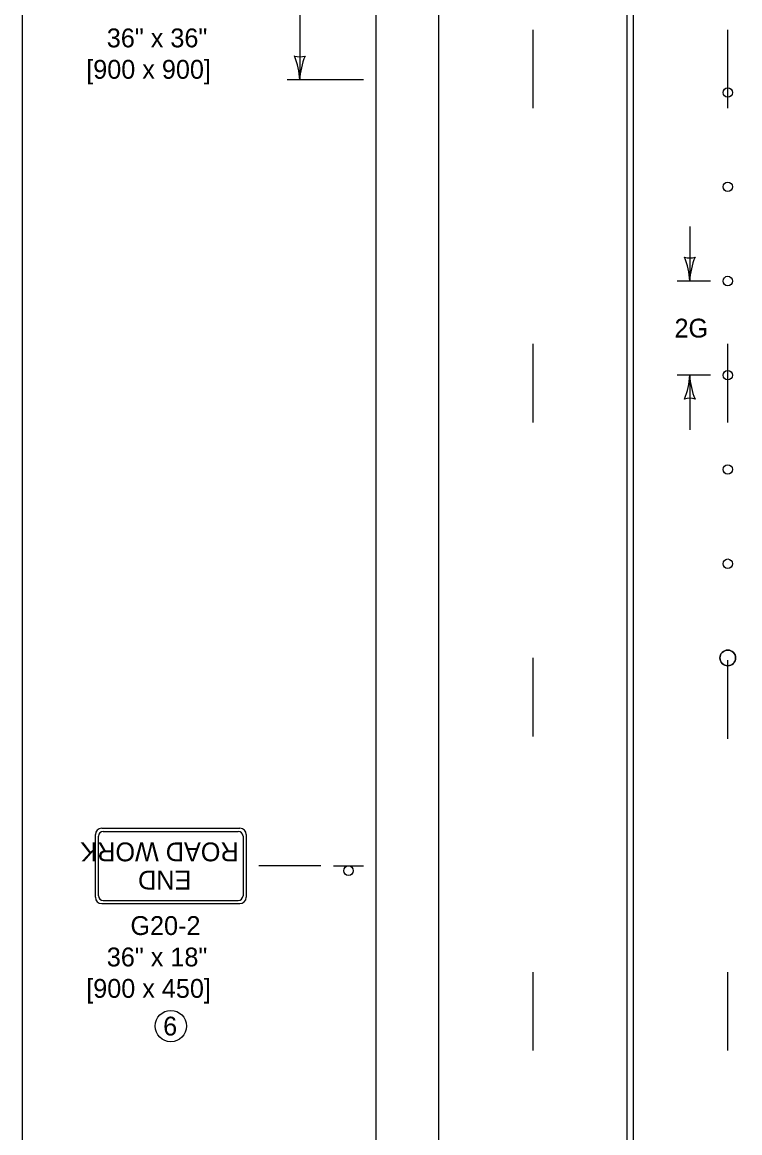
# Model space of a CAD drawing. Extents: x 49991.4 to 50021, y 49987.6 to 50011.4.
# Drawn here: x 50000.336 to 50002.621, y 50003.296 to 50006.831 of the extents above; entities that cross this region are included whole.
import ezdxf

# ---------------------------------------------------------------- set-up
doc = ezdxf.new("R2010")
doc.units = 0
for name, color, linetype in [('Level 1', 7, 'Continuous'), ('Level 2', 7, 'Continuous'), ('Level 3', 7, 'Continuous')]:
    doc.layers.add(name, color=color, linetype=linetype)

msp = doc.modelspace()

# ---------------------------------------------------------------- linework, layer by layer
at = {"layer": 'Level 1'}
for p, q in [((50001.4626, 50001.1514), (50001.4626, 50009.2134)), ((50001.6625, 50001.1514), (50001.6625, 50009.2134)), ((50002.2625, 50001.1514), (50002.2625, 50009.2134)), ((50002.2825, 50001.1514), (50002.2825, 50009.2134)), ((50001.9626, 50006.5574), (50001.9626, 50006.8074)), ((50002.5826, 50006.5574), (50002.5826, 50006.8074)), ((50001.9626, 50005.5574), (50001.9626, 50005.8074)), ((50002.5826, 50005.5574), (50002.5826, 50005.8074)), ((50001.9626, 50004.5574), (50001.9626, 50004.8074)), ((50002.5822, 50004.5501), (50002.5822, 50004.8001)), ((50000.5889, 50004.2653), (50001.0289, 50004.2653)), ((50000.5938, 50004.2553), (50001.0238, 50004.2553)), ((50000.5688, 50004.0453), (50000.5688, 50004.2453)), ((50000.5788, 50004.0503), (50000.5788, 50004.2403)), ((50001.0388, 50004.2403), (50001.0388, 50004.0503)), ((50001.0488, 50004.2453), (50001.0488, 50004.0453)), ((50001.3266, 50004.1453), (50001.4226, 50004.1453)), ((50000.5888, 50004.0253), (50001.0288, 50004.0253)), ((50000.5938, 50004.0353), (50001.0238, 50004.0353)), ((50001.9626, 50003.5574), (50001.9626, 50003.8074)), ((50002.5826, 50003.5574), (50002.5826, 50003.8074))]:
    msp.add_line(p, q, dxfattribs=at)
msp.add_lwpolyline([(50008.6146, 50011.2628), (50000.3356, 50011.2628), (50000.3356, 50000.0624), (50008.6146, 50000.0624)], close=True, dxfattribs=at)
for centre, radius in [((50002.5826, 50006.6074), 0.015), ((50002.5826, 50006.3074), 0.015), ((50002.5826, 50006.0074), 0.015), ((50002.5826, 50005.7074), 0.015), ((50002.5826, 50005.4074), 0.015), ((50002.5826, 50005.1074), 0.015), ((50002.5826, 50004.8074), 0.025), ((50001.3747, 50004.1301), 0.0152)]:
    msp.add_circle(centre, radius, dxfattribs=at)
for centre, radius, start, end in [((50002.5826, 50004.8074), 0.025, 0, 180), ((50002.5826, 50004.8074), 0.025, 180, 0), ((50000.5889, 50004.2453), 0.02, 90, 180), ((50000.5938, 50004.2403), 0.015, 90, 180), ((50001.0238, 50004.2403), 0.015, 360, 90), ((50001.0289, 50004.2453), 0.02, 360, 90), ((50000.5888, 50004.0453), 0.02, 180, 270), ((50000.5938, 50004.0503), 0.015, 180, 270), ((50001.0238, 50004.0503), 0.015, 270, 360), ((50001.0288, 50004.0453), 0.02, 270, 360)]:
    msp.add_arc(centre, radius, start, end, dxfattribs=at)
at = {"layer": 'Level 2'}
msp.add_circle((50000.8089, 50003.6352), 0.0501, dxfattribs=at)
at = {"layer": 'Level 3'}
for p, q in [((50001.2196, 50007.2477), (50001.2196, 50006.6477)), ((50001.4226, 50006.6477), (50001.1796, 50006.6477)), ((50002.4614, 50006.1808), (50002.4614, 50006.0074)), ((50002.5276, 50006.0074), (50002.4214, 50006.0074)), ((50002.5276, 50005.7074), (50002.4214, 50005.7074)), ((50002.4614, 50005.7074), (50002.4614, 50005.534)), ((50001.2866, 50004.1453), (50001.0888, 50004.1453))]:
    msp.add_line(p, q, dxfattribs=at)
for centre, radius, start, end in [((50001.2196, 50006.7759), 0.0548, 252.1388, 287.8612), ((50000.9869, 50006.6362), 0.233, 2.8273, 22.0772), ((50001.4417, 50006.6385), 0.2223, 157.456, 177.6395), ((50002.2393, 50005.9982), 0.2223, 2.3605, 22.544), ((50002.4614, 50006.1356), 0.0548, 252.1388, 287.8612), ((50002.6941, 50005.9959), 0.233, 157.9228, 177.1727), ((50002.2287, 50005.7189), 0.233, 337.9228, 357.1727), ((50002.6836, 50005.7166), 0.2223, 182.3605, 202.544), ((50002.4614, 50005.5792), 0.0548, 72.1388, 107.8612)]:
    msp.add_arc(centre, radius, start, end, dxfattribs=at)

# ---------------------------------------------------------------- texts
at = {"layer": 'Level 1'}
for s, p in [('ROAD WORK', (50001.0247, 50004.2199)), ('END', (50000.874, 50004.1299))]:
    msp.add_text(s, height=0.06, rotation=180, dxfattribs=at).set_placement(p)
at = {"layer": 'Level 2'}
for s, p in [('36" x 36"', (50000.605, 50006.7513)), ('[900 x 900]', (50000.5395, 50006.6513)), ('G20-2', (50000.6803, 50003.9253)), ('36" x 18"', (50000.605, 50003.8253)), ('[900 x 450]', (50000.5395, 50003.7253)), ('6', (50000.7845, 50003.6053))]:
    msp.add_text(s, height=0.06, dxfattribs=at).set_placement(p)
msp.add_text('2G', height=0.06, rotation=360, dxfattribs=at).set_placement((50002.4128, 50005.8274))

doc.saveas('drawing.dxf')
